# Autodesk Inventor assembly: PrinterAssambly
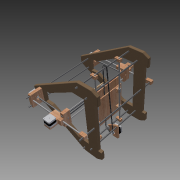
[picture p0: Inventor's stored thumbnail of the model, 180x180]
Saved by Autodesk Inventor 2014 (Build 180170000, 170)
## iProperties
Created: 2013-12
Part Number: PrinterAssambly
Document SubType Name: Assembly
Designer: Bram
Author: Bram
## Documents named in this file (28)
- D:\gDrive\Google Drive\Hobby\3D Printer\3D printer\Inventor\PrinterAssambly.iam
- D:\gDrive\Google Drive\Hobby\3D Printer\3D printer\Inventor\A_Frame_V2.ipt
- D:\gDrive\Google Drive\Hobby\3D Printer\3D printer\Inventor\Rods\370_Thread.ipt
- D:\gDrive\Google Drive\Hobby\3D Printer\3D printer\Inventor\Rods\508_Thread.ipt
- D:\gDrive\Google Drive\Hobby\3D Printer\3D printer\Inventor\Z_MotorMount_RodHolder__Part1_V2.ipt
- D:\gDrive\Google Drive\Hobby\3D Printer\3D printer\Inventor\Rods\354_Side_Up.ipt
- D:\gDrive\Google Drive\Hobby\3D Printer\3D printer\Inventor\Z_MotorMount_RodHolder_Part2_V2.ipt
- D:\gDrive\Google Drive\Hobby\3D Printer\3D printer\Inventor\NEMA17.ipt
- D:\gDrive\Google Drive\Hobby\3D Printer\3D printer\Inventor\Rods\210_Thread.ipt
- D:\gDrive\Google Drive\Hobby\3D Printer\3D printer\Inventor\Top_RodHolder.ipt
- D:\gDrive\Google Drive\Hobby\3D Printer\3D printer\Inventor\Rods\457.ipt
- D:\gDrive\Google Drive\Hobby\3D Printer\3D printer\Inventor\X_Top_MotorSide_V3.ipt
- D:\gDrive\Google Drive\Hobby\3D Printer\3D printer\Inventor\LM8UU.ipt
- D:\gDrive\Google Drive\Hobby\3D Printer\3D printer\Inventor\X_Top_PullySide_V2.ipt
- D:\gDrive\Google Drive\Hobby\3D Printer\3D printer\Inventor\X_Bottem_MotorSide_V3.ipt
- D:\gDrive\Google Drive\Hobby\3D Printer\3D printer\Inventor\PrinterAssambly\Design Accelerator\Synchronous Belts Transmission1.iam
- D:\gDrive\Google Drive\Hobby\3D Printer\3D printer\Inventor\Y_MotorMount.ipt
- D:\gDrive\Google Drive\Hobby\3D Printer\3D printer\Inventor\608ZZBearing.ipt
- D:\gDrive\Google Drive\Hobby\3D Printer\3D printer\Inventor\Timping Pully.ipt
- D:\gDrive\Google Drive\Hobby\3D Printer\3D printer\Inventor\X_Carriage_WithBearings.ipt
- D:\gDrive\Google Drive\Hobby\3D Printer\3D printer\Inventor\BarClamp_V2.ipt
- D:\gDrive\Google Drive\Hobby\3D Printer\3D printer\Inventor\Rods\406.ipt
- D:\gDrive\Google Drive\Hobby\3D Printer\3D printer\Inventor\Y_RodClam_Bed.ipt
- D:\gDrive\Google Drive\Hobby\3D Printer\3D printer\Inventor\Print_BottemPlate.ipt
- D:\gDrive\Google Drive\Hobby\3D Printer\3D printer\Inventor\Print_TopPlate.ipt
- D:\gDrive\Google Drive\Hobby\3D Printer\3D printer\Inventor\Heatbed_Standoff.ipt
- D:\gDrive\Google Drive\Hobby\3D Printer\3D printer\Inventor\Heatbed.ipt
- D:\gDrive\Google Drive\Hobby\3D Printer\3D printer\Inventor\PrinterAssambly\Design Accelerator\Synchronous Belts Transmission2.iam
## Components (59 placed, 26 different names)
1. A_Frame_V2:1 — Mate:8, Mate:37
2. A_Frame_V2:2 — Mate:4, Flush:4, Mate:5, Flush:5, Mate:6, Flush:6, Mate:7, Flush:7, Mate:9, Mate:10, Mate:14, Mate:17
3. 370_Thread:3 — Mate:4, Flush:4, Mate:8, Mate:88, Mate:91, Mate:99, Mate:100
4. 370_Thread:4 — Mate:5, Flush:5, Mate:87
5. 370_Thread:5 — Mate:7, Flush:7
6. 370_Thread:6 — Mate:6, Flush:6, Mate:92, Mate:101, Mate:102
7. 508_Thread:1 — Mate:9, Mate:15, Mate:19, Mate:36
8. 508_Thread:2 — Mate:10, Mate:16, Mate:20, Mate:35, Mate:39
9. 508_Thread:3 — Mate:14, Mate:26, Mate:46
10. Z_MotorMount_RodHolder__Part1_V2:1 — Mate:15, Mate:16, Mate:17, Mate:18, Mate:21, Mate:22
11. 354_Side_Up:1 — Mate:18, Mate:25, Mate:62, Mate:69
12. Z_MotorMount_RodHolder_Part2_V2:1 — Mate:19, Mate:20, Mate:21
13. NEMA17:1 — Mate:22, Mate:23, Mate:24
14. 210_Thread:1 — Mate:23, Mate:24, Mate:63, Mate:68
15. Top_RodHolder:1 — Mate:25, Mate:26
16. Z_MotorMount_RodHolder__Part1_V2:2 — Mate:35, Mate:36, Mate:37, Mate:38, Mate:40, Mate:41, Mate:42
17. 354_Side_Up:2 — Mate:38, Mate:45, Mate:66, Mate:72
18. Z_MotorMount_RodHolder_Part2_V2:2 — Mate:39, Mate:40
19. NEMA17:3 — Mate:41, Mate:42, Mate:43, Mate:44
20. 210_Thread:2 — Mate:43, Mate:44, Mate:67, Mate:71
21. Top_RodHolder:2 — Mate:45, Mate:46
22. X_Top_MotorSide_V3:1 — Mate:58, Mate:59, Mate:60, Mate:61, Mate:63, Mate:70
23. LM8UU:1 — Mate:58, Mate:59, Mate:62
24. NEMA17:4 — Mate:60, Mate:61, Mate:83, Mate:84
25. X_Top_PullySide_V2:1 — Mate:65, Flush:10, Mate:67, Mate:73, Mate:82
26. LM8UU:2 — Mate:65, Flush:10, Mate:66
27. X_Bottem_MotorSide_V3:1 — Mate:68, Mate:69, Mate:70, Mate:75, Mate:76
28. X_Bottem_MotorSide_V3:2 — Mate:71, Mate:72, Mate:73, Mate:74, Flush:11, Mate:77, Flush:12
29. 457:1 — Mate:74, Mate:75, Flush:11, Mate:97
30. 457:2 — Mate:76, Mate:77, Flush:12, Mate:98
31. Synchronous Belts Transmission:1 [sub-assembly] — Mate:82, Mate:83, Mate:84
32. Y_MotorMount:1 — Mate:87, Mate:88, Mate:89, Mate:90, Flush:13
33. NEMA17:5 — Mate:89, Mate:90, Mate:95
34. 608ZZBearing:1 — Mate:91, Mate:93, Mate:96, Flush:21
35. 608ZZBearing:2 — Mate:92, Mate:93
36. Timping Pully:1 — Mate:95, Mate:96, Flush:13
37. X_Carriage_WithBearings:1 — Mate:97, Mate:98
38. BarClamp_V2:1 — Mate:99, Mate:105, Flush:15, Mate:107
39. BarClamp_V2:2 — Mate:100, Mate:103, Flush:14, Mate:107
40. BarClamp_V2:3 — Mate:102, Mate:106
41. BarClamp_V2:4 — Mate:101, Mate:104
42. 406:1 — Mate:103, Flush:14, Mate:104, Mate:108, Mate:109
43. 406:2 — Mate:105, Flush:15, Mate:106, Mate:110, Mate:111
44. LM8UU:3 — Mate:108, Mate:112, Mate:113
45. LM8UU:4 — Mate:110, Mate:116, Flush:18
46. LM8UU:5 — Mate:109, Mate:114, Flush:16
47. LM8UU:6 — Mate:111, Mate:115, Flush:17
48. Y_RodClam_Bed:1 — Mate:116, Flush:18, Mate:117, Mate:118, Mate:122, Mate:123
49. Y_RodClam_Bed:3 — Mate:112, Mate:113, Mate:119, Mate:120, Flush:19
50. Y_RodClam_Bed:4 — Mate:114, Flush:16, Mate:119, Mate:120, Mate:121
51. Y_RodClam_Bed:5 — Mate:115, Flush:17, Mate:117, Mate:118, Mate:121
52. Print_BottemPlate:1 — Mate:122, Mate:123, Flush:19, Mate:124, Mate:125, Flush:20
53. Print_TopPlate:1 — Mate:124, Mate:125, Flush:20, Mate:126, Mate:127, Mate:128, Mate:129, Mate:130, Mate:131, Mate:132, Mate:133
54. Heatbed_Standoff:1 — Mate:126, Mate:127, Mate:136
55. Heatbed_Standoff:2 — Mate:128, Mate:129
56. Heatbed_Standoff:3 — Mate:130, Mate:131, Mate:134, Mate:135
57. Heatbed_Standoff:4 — Mate:132, Mate:133
58. Heatbed:1 — Mate:134, Mate:135, Mate:136
59. Synchronous Belts Transmission:2 [sub-assembly] — Flush:21
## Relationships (119: Mate 103, Flush 16)
- Mate:4: A_Frame_V2:2 ↔ 370_Thread:3
- Flush:4: A_Frame_V2:2 ↔ 370_Thread:3
- Mate:5: A_Frame_V2:2 ↔ 370_Thread:4
- Flush:5: A_Frame_V2:2 ↔ 370_Thread:4
- Mate:6: A_Frame_V2:2 ↔ 370_Thread:6
- Flush:6: A_Frame_V2:2 ↔ 370_Thread:6
- Mate:7: A_Frame_V2:2 ↔ 370_Thread:5
- Flush:7: A_Frame_V2:2 ↔ 370_Thread:5
- Mate:8: A_Frame_V2:1 ↔ 370_Thread:3
- Mate:9: A_Frame_V2:2 ↔ 508_Thread:1
- Mate:10: A_Frame_V2:2 ↔ 508_Thread:2
- Mate:14: A_Frame_V2:2 ↔ 508_Thread:3
- Mate:15: 508_Thread:1 ↔ Z_MotorMount_RodHolder__Part1_V2:1
- Mate:16: 508_Thread:2 ↔ Z_MotorMount_RodHolder__Part1_V2:1
- Mate:17: A_Frame_V2:2 ↔ Z_MotorMount_RodHolder__Part1_V2:1
- Mate:18: Z_MotorMount_RodHolder__Part1_V2:1 ↔ 354_Side_Up:1
- Mate:19: 508_Thread:1 ↔ Z_MotorMount_RodHolder_Part2_V2:1
- Mate:20: 508_Thread:2 ↔ Z_MotorMount_RodHolder_Part2_V2:1
- Mate:21: Z_MotorMount_RodHolder__Part1_V2:1 ↔ Z_MotorMount_RodHolder_Part2_V2:1
- Mate:22: Z_MotorMount_RodHolder__Part1_V2:1 ↔ NEMA17:1
- Mate:23: NEMA17:1 ↔ 210_Thread:1
- Mate:24: NEMA17:1 ↔ 210_Thread:1
- Mate:25: 354_Side_Up:1 ↔ Top_RodHolder:1
- Mate:26: 508_Thread:3 ↔ Top_RodHolder:1
- Mate:35: 508_Thread:2 ↔ Z_MotorMount_RodHolder__Part1_V2:2
- Mate:36: 508_Thread:1 ↔ Z_MotorMount_RodHolder__Part1_V2:2
- Mate:37: A_Frame_V2:1 ↔ Z_MotorMount_RodHolder__Part1_V2:2
- Mate:38: Z_MotorMount_RodHolder__Part1_V2:2 ↔ 354_Side_Up:2
- Mate:39: 508_Thread:2 ↔ Z_MotorMount_RodHolder_Part2_V2:2
- Mate:40: Z_MotorMount_RodHolder__Part1_V2:2 ↔ Z_MotorMount_RodHolder_Part2_V2:2
- Mate:41: Z_MotorMount_RodHolder__Part1_V2:2 ↔ NEMA17:3
- Mate:42: Z_MotorMount_RodHolder__Part1_V2:2 ↔ NEMA17:3
- Mate:43: NEMA17:3 ↔ 210_Thread:2
- Mate:44: NEMA17:3 ↔ 210_Thread:2
- Mate:45: 354_Side_Up:2 ↔ Top_RodHolder:2
- Mate:46: 508_Thread:3 ↔ Top_RodHolder:2
- Mate:58: X_Top_MotorSide_V3:1 ↔ LM8UU:1
- Mate:59: X_Top_MotorSide_V3:1 ↔ LM8UU:1
- Mate:60: X_Top_MotorSide_V3:1 ↔ NEMA17:4
- Mate:61: X_Top_MotorSide_V3:1 ↔ NEMA17:4
- Mate:62: 354_Side_Up:1 ↔ LM8UU:1
- Mate:63: 210_Thread:1 ↔ X_Top_MotorSide_V3:1
- Mate:65: X_Top_PullySide_V2:1 ↔ LM8UU:2
- Flush:10: X_Top_PullySide_V2:1 ↔ LM8UU:2
- Mate:66: 354_Side_Up:2 ↔ LM8UU:2
- Mate:67: 210_Thread:2 ↔ X_Top_PullySide_V2:1
- Mate:68: 210_Thread:1 ↔ X_Bottem_MotorSide_V3:1
- Mate:69: 354_Side_Up:1 ↔ X_Bottem_MotorSide_V3:1
- Mate:70: X_Top_MotorSide_V3:1 ↔ X_Bottem_MotorSide_V3:1
- Mate:71: 210_Thread:2 ↔ X_Bottem_MotorSide_V3:2
- Mate:72: 354_Side_Up:2 ↔ X_Bottem_MotorSide_V3:2
- Mate:73: X_Top_PullySide_V2:1 ↔ X_Bottem_MotorSide_V3:2
- Mate:74: X_Bottem_MotorSide_V3:2 ↔ 457:1
- Mate:75: X_Bottem_MotorSide_V3:1 ↔ 457:1
- Flush:11: X_Bottem_MotorSide_V3:2 ↔ 457:1
- Mate:76: X_Bottem_MotorSide_V3:1 ↔ 457:2
- Mate:77: X_Bottem_MotorSide_V3:2 ↔ 457:2
- Flush:12: X_Bottem_MotorSide_V3:2 ↔ 457:2
- Mate:82: X_Top_PullySide_V2:1 ↔ Synchronous Belts Transmission:1
- Mate:83: NEMA17:4 ↔ Synchronous Belts Transmission:1
- Mate:84: NEMA17:4 ↔ Synchronous Belts Transmission:1
- Mate:87: 370_Thread:4 ↔ Y_MotorMount:1
- Mate:88: 370_Thread:3 ↔ Y_MotorMount:1
- Mate:89: Y_MotorMount:1 ↔ NEMA17:5
- Mate:90: Y_MotorMount:1 ↔ NEMA17:5
- Mate:91: 370_Thread:3 ↔ 608ZZBearing:1
- Mate:92: 370_Thread:6 ↔ 608ZZBearing:2
- Mate:93: 608ZZBearing:1 ↔ 608ZZBearing:2
- Mate:95: NEMA17:5 ↔ Timping Pully:1
- Mate:96: 608ZZBearing:1 ↔ Timping Pully:1
- Flush:13: Y_MotorMount:1 ↔ Timping Pully:1
- Mate:97: 457:1 ↔ X_Carriage_WithBearings:1
- Mate:98: 457:2 ↔ X_Carriage_WithBearings:1
- Mate:99: 370_Thread:3 ↔ BarClamp_V2:1
- Mate:100: 370_Thread:3 ↔ BarClamp_V2:2
- Mate:101: 370_Thread:6 ↔ BarClamp_V2:4
- Mate:102: 370_Thread:6 ↔ BarClamp_V2:3
- Mate:103: BarClamp_V2:2 ↔ 406:1
- Flush:14: BarClamp_V2:2 ↔ 406:1
- Mate:104: BarClamp_V2:4 ↔ 406:1
- Mate:105: BarClamp_V2:1 ↔ 406:2
- Flush:15: BarClamp_V2:1 ↔ 406:2
- Mate:106: BarClamp_V2:3 ↔ 406:2
- Mate:107: BarClamp_V2:1 ↔ BarClamp_V2:2
- Mate:108: 406:1 ↔ LM8UU:3
- Mate:109: 406:1 ↔ LM8UU:5
- Mate:110: 406:2 ↔ LM8UU:4
- Mate:111: 406:2 ↔ LM8UU:6
- Mate:112: LM8UU:3 ↔ Y_RodClam_Bed:3
- Mate:113: LM8UU:3 ↔ Y_RodClam_Bed:3
- Mate:114: LM8UU:5 ↔ Y_RodClam_Bed:4
- Flush:16: LM8UU:5 ↔ Y_RodClam_Bed:4
- Mate:115: LM8UU:6 ↔ Y_RodClam_Bed:5
- Flush:17: LM8UU:6 ↔ Y_RodClam_Bed:5
- Mate:116: LM8UU:4 ↔ Y_RodClam_Bed:1
- Flush:18: LM8UU:4 ↔ Y_RodClam_Bed:1
- Mate:117: Y_RodClam_Bed:1 ↔ Y_RodClam_Bed:5
- Mate:118: Y_RodClam_Bed:1 ↔ Y_RodClam_Bed:5
- Mate:119: Y_RodClam_Bed:3 ↔ Y_RodClam_Bed:4
- Mate:120: Y_RodClam_Bed:3 ↔ Y_RodClam_Bed:4
- Mate:121: Y_RodClam_Bed:4 ↔ Y_RodClam_Bed:5
- Mate:122: Y_RodClam_Bed:1 ↔ Print_BottemPlate:1
- Mate:123: Y_RodClam_Bed:1 ↔ Print_BottemPlate:1
- Flush:19: Y_RodClam_Bed:3 ↔ Print_BottemPlate:1
- Mate:124: Print_BottemPlate:1 ↔ Print_TopPlate:1
- Mate:125: Print_BottemPlate:1 ↔ Print_TopPlate:1
- Flush:20: Print_BottemPlate:1 ↔ Print_TopPlate:1
- Mate:126: Print_TopPlate:1 ↔ Heatbed_Standoff:1
- Mate:127: Print_TopPlate:1 ↔ Heatbed_Standoff:1
- Mate:128: Print_TopPlate:1 ↔ Heatbed_Standoff:2
- Mate:129: Print_TopPlate:1 ↔ Heatbed_Standoff:2
- Mate:130: Print_TopPlate:1 ↔ Heatbed_Standoff:3
- Mate:131: Print_TopPlate:1 ↔ Heatbed_Standoff:3
- Mate:132: Print_TopPlate:1 ↔ Heatbed_Standoff:4
- Mate:133: Print_TopPlate:1 ↔ Heatbed_Standoff:4
- Mate:134: Heatbed_Standoff:3 ↔ Heatbed:1
- Mate:135: Heatbed_Standoff:3 ↔ Heatbed:1
- Mate:136: Heatbed_Standoff:1 ↔ Heatbed:1
- Flush:21: 608ZZBearing:1 ↔ Synchronous Belts Transmission:2
